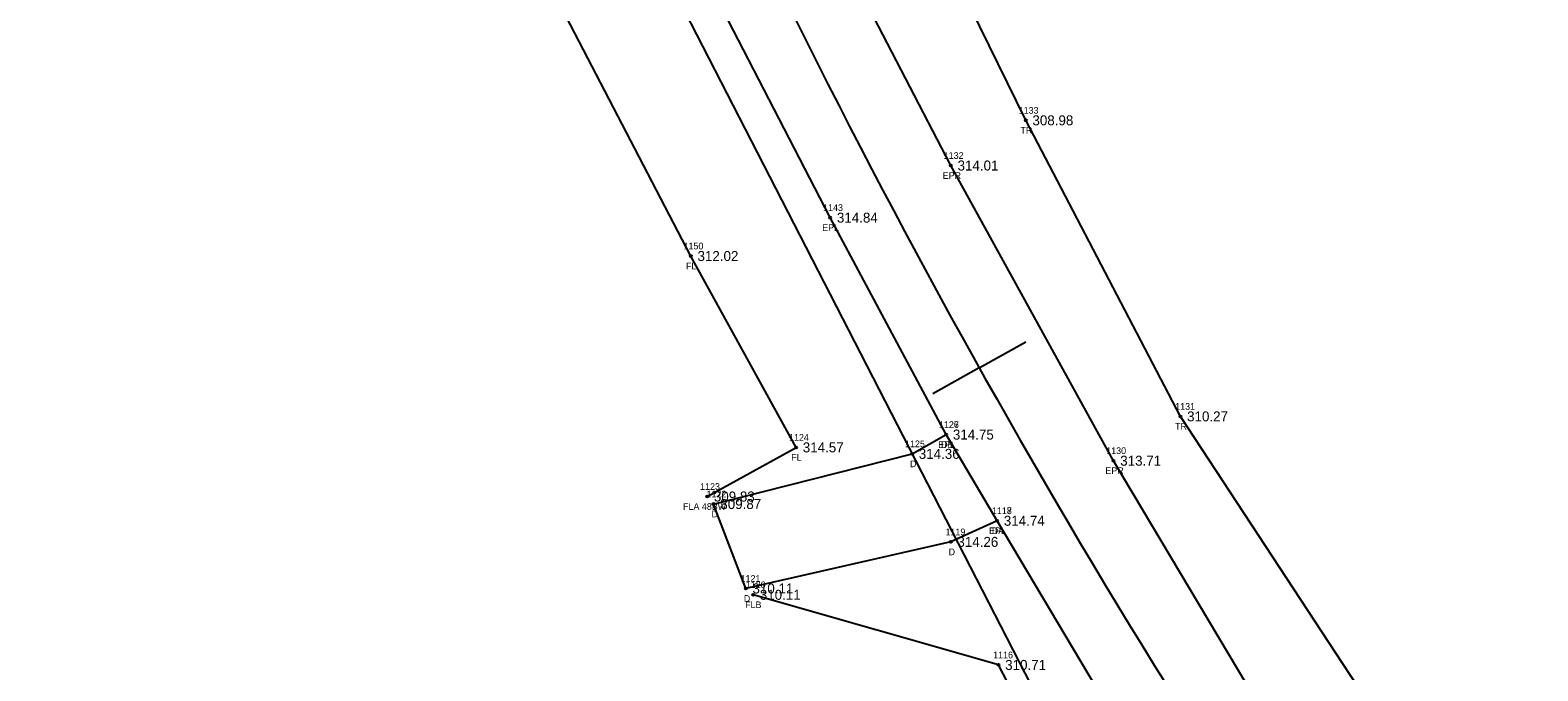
# Model space of a CAD drawing. Extents: x 1865045 to 1867370, y 910391 to 914218.
# Drawn here: x 1866393.9 to 1866620.1, y 910723.1 to 910819.2 of the extents above; entities that cross this region are included whole.
import ezdxf

# ---------------------------------------------------------------- set-up
doc = ezdxf.new("R2010")
doc.units = 0
for name, color, linetype in [('RD_EX_Driveway', 7, 'Continuous'), ('RD_EX_Driveway_txCode', 7, 'Continuous'), ('RD_EX_Fence_Other', 7, 'Continuous'), ('RD_EX_Fence_Other_txCode', 7, 'Continuous'), ('RD_EX_Road', 7, 'Continuous'), ('RD_EX_Road_txCode', 7, 'Continuous'), ('RD_EX_TX_Driveway_ELEV', 7, 'Continuous'), ('RD_EX_TX_Fence_Other_ELEV', 7, 'Continuous'), ('RD_EX_TX_Road_ELEV', 7, 'Continuous'), ('RD_EX_TX_VEG_ELEV', 7, 'Continuous'), ('RD_EX_VEG', 7, 'Continuous'), ('RD_EX_VEG_txCode', 7, 'Continuous'), ('RD_HC_Cl', 7, 'Continuous'), ('RD_HC_Data_Tic', 7, 'Continuous'), ('RD_SMD_Locator', 7, 'Continuous')]:
    doc.layers.add(name, color=color, linetype=linetype)

msp = doc.modelspace()

# ---------------------------------------------------------------- linework, layer by layer
at = {"layer": 'RD_EX_Driveway'}
msp.add_lwpolyline([(1866538.98, 910745.57), (1866532.01, 910742.4), (1866501.27, 910735.41), (1866496.45, 910748.08), (1866526.22, 910755.61), (1866531.34, 910758.5)], dxfattribs=at)
at = {"layer": 'RD_EX_Fence_Other'}
for points in [[(1866495.48, 910749.21), (1866508.82, 910756.58), (1866493.03, 910785.29), (1866469.81, 910829.93), (1866443.69, 910882.22), (1866422.34, 910922.89), (1866379.46, 911022.29), (1866316.24, 911049.61), (1866298.72, 911056.62), (1866262.33, 911070.09)], [(1866575.75, 910576.9), (1866560.55, 910615.03), (1866556.56, 910662.5), (1866565.78, 910678.27), (1866557.83, 910687.95), (1866539.18, 910723.94), (1866502.37, 910734.46)]]:
    msp.add_lwpolyline(points, dxfattribs=at)
at = {"layer": 'RD_EX_Road'}
for points in [[(1866813.99, 910446.88), (1866778.44, 910479.3), (1866742.34, 910514.45), (1866706.87, 910550.71), (1866695.16, 910564.33), (1866672.6, 910589.75), (1866641.04, 910629.03), (1866609.7, 910670.28), (1866582.23, 910711.25), (1866556.44, 910754.58), (1866532.04, 910798.87), (1866507.56, 910846.03), (1866483.5, 910895.43), (1866461.16, 910941.96), (1866414.86, 911037.95), (1866406.11, 911034.1)], [(1866800.58, 910432.45), (1866764.32, 910465.74), (1866727.39, 910500.95), (1866691.9, 910537.68), (1866657.44, 910577.07), (1866624.97, 910617.36), (1866593.69, 910658.89), (1866565.16, 910701.48), (1866538.98, 910745.57), (1866531.34, 910758.5), (1866513.94, 910791.05), (1866489.48, 910838.44), (1866465.73, 910886.02), (1866443.47, 910933.62), (1866397.5, 911029.82), (1866406.11, 911034.1)]]:
    msp.add_lwpolyline(points, dxfattribs=at)
at = {"layer": 'RD_EX_VEG'}
for points in [[(1866625.81, 910677.72), (1866594.09, 910719.14), (1866566.47, 910761.23), (1866543.27, 910805.65), (1866519.83, 910853.48), (1866496.01, 910901.81), (1866477.92, 910951.04)], [(1866770.74, 910392.93), (1866734.38, 910438.07), (1866709.99, 910485.53), (1866679.02, 910526.15), (1866645.41, 910567.43), (1866612.91, 910609.64), (1866580.57, 910649.92), (1866452.86, 910898.44)]]:
    msp.add_lwpolyline(points, dxfattribs=at)
at = {"layer": 'RD_HC_Cl'}
msp.add_arc((1867567.42, 911345.48), 1181.58, 205.67399, 227.8297, dxfattribs=at)
at = {"layer": 'RD_HC_Data_Tic'}
for q in [(1866543.28, 910772.4), (1866529.31, 910764.59)]:
    msp.add_line((1866536.3, 910768.49), q, dxfattribs=at)
at = {"layer": 'RD_SMD_Locator'}
for centre in [(1866543.27, 910805.65), (1866532.04, 910798.87), (1866513.94, 910791.05), (1866493.03, 910785.29), (1866566.47, 910761.23), (1866531.34, 910758.5), (1866531.34, 910758.5), (1866508.82, 910756.58), (1866526.22, 910755.61), (1866556.44, 910754.58), (1866495.48, 910749.21), (1866496.45, 910748.08), (1866538.98, 910745.57), (1866538.98, 910745.57), (1866532.01, 910742.4), (1866501.27, 910735.41), (1866502.37, 910734.46), (1866539.18, 910723.94)]:
    msp.add_circle(centre, 0.15, dxfattribs=at)

# ---------------------------------------------------------------- texts
at = {"layer": 'RD_EX_Driveway_txCode'}
for s, p in [('1127', (1866530.27, 910759.5)), ('1125', (1866525.16, 910756.61)), ('DB', (1866530.56, 910756.5)), ('D', (1866525.91, 910753.61)), ('1122', (1866495.38, 910749.08)), ('D', (1866496.14, 910746.08)), ('1118', (1866538.2, 910746.57)), ('1119', (1866531.23, 910743.4)), ('DA', (1866538.18, 910743.57)), ('D', (1866531.7, 910740.4)), ('1121', (1866500.49, 910736.41)), ('D', (1866500.97, 910733.41))]:
    msp.add_text(s, height=1, dxfattribs=at).set_placement(p)
at = {"layer": 'RD_EX_Fence_Other_txCode'}
for s, p in [('1150', (1866491.93, 910786.29)), ('FL', (1866492.3, 910783.29)), ('1124', (1866507.76, 910757.58)), ('FL', (1866508.09, 910754.58)), ('1123', (1866494.42, 910750.21)), ('FLA 48BW', (1866491.86, 910747.21)), ('1120', (1866501.27, 910735.46)), ('FLB', (1866501.17, 910732.46)), ('1116', (1866538.38, 910724.94))]:
    msp.add_text(s, height=1, dxfattribs=at).set_placement(p)
at = {"layer": 'RD_EX_Road_txCode'}
for s, p in [('1132', (1866530.97, 910799.87)), ('EPR', (1866530.81, 910796.87)), ('1143', (1866512.87, 910792.05)), ('EPL', (1866512.73, 910789.05)), ('1126', (1866530.25, 910759.5)), ('EPL', (1866530.13, 910756.5)), ('1130', (1866555.34, 910755.58)), ('EPR', (1866555.21, 910752.58)), ('1117', (1866538.2, 910746.57)), ('EPL', (1866537.77, 910743.57))]:
    msp.add_text(s, height=1, dxfattribs=at).set_placement(p)
at = {"layer": 'RD_EX_TX_Driveway_ELEV'}
for s, p in [('314.75', (1866532.34, 910757.75)), ('314.36', (1866527.22, 910754.86)), ('309.87', (1866497.45, 910747.33)), ('314.74', (1866539.98, 910744.82)), ('314.26', (1866533.01, 910741.65)), ('310.11', (1866502.27, 910734.66))]:
    msp.add_text(s, height=1.5, dxfattribs=at).set_placement(p)
at = {"layer": 'RD_EX_TX_Fence_Other_ELEV'}
for s, p in [('312.02', (1866494.03, 910784.54)), ('314.57', (1866509.82, 910755.83)), ('309.83', (1866496.48, 910748.46)), ('310.11', (1866503.37, 910733.71)), ('310.71', (1866540.18, 910723.19))]:
    msp.add_text(s, height=1.5, dxfattribs=at).set_placement(p)
at = {"layer": 'RD_EX_TX_Road_ELEV'}
for s, p in [('314.01', (1866533.04, 910798.12)), ('314.84', (1866514.94, 910790.3)), ('314.75', (1866532.34, 910757.75)), ('313.71', (1866557.44, 910753.83)), ('314.74', (1866539.98, 910744.82))]:
    msp.add_text(s, height=1.5, dxfattribs=at).set_placement(p)
at = {"layer": 'RD_EX_TX_VEG_ELEV'}
for s, p in [('308.98', (1866544.27, 910804.9)), ('310.27', (1866567.47, 910760.48))]:
    msp.add_text(s, height=1.5, dxfattribs=at).set_placement(p)
at = {"layer": 'RD_EX_VEG_txCode'}
for s, p in [('1133', (1866542.21, 910806.65)), ('TR', (1866542.47, 910803.65)), ('1131', (1866565.69, 910762.23)), ('TR', (1866565.67, 910759.23))]:
    msp.add_text(s, height=1, dxfattribs=at).set_placement(p)

doc.saveas('drawing.dxf')
